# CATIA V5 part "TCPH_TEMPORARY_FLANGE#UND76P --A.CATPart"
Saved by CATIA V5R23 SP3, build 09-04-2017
Part number: TCPH_TEMPORARY_FLANGE#UND758
Revision: --A
Nomenclature: _
Description: TCPH_TEMPORARY_FLANGE
Property "ID": "UND758"
Property "AT": "PD"
Property "REP": "CM"
Property "External Part ID": "_"
Property "Description Modification": "FDR Model"
Property "PREF": "Y"
Property "LONG": "_"
Property "PBS 1": "24"
Property "PBS 2": "CR"
Property "PBS 3": "LC"
Property "DEPT": "_"
Property "DIVN": "_"
Property "GROUP": "_"
Property "UNIT": "_"
Property "PARTY": "_"
Property "RO": "BHARDWA"
Property "RE": "VITUPIG"
Property "PRO": "---"
Property "Change Type": "Minor"
Property "Maturity Level": "CD"
Property "Export Number": "_"
Property "Description Documents": "_"
Property "BOM": "_"
Property "User In Enovia": "VAUQUEJ"
Property "Object Type": "_"
Property "CADENAS_ID": "_"
Property "Life Cycle Status": "Approved"
Bounding box of the stored display mesh (mm): x 16800 to 17545, y -1350 to 1350, z -6273 to -2983
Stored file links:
  C:\Users\pandeym\Desktop\__TCPH\TCPH_TEMPORARY_FLANGE#UND76P --A.CATPart
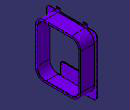
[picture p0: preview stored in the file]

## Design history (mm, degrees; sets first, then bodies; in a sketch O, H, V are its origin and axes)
Set1
  Sketch1 "CR_DOCKING_PORT_CONTACT_INNER_SHELL", origin (17545, 0, 0), H (0, 1, 0), V (0, 0, 1), geometry linked from another document
  Sketch2 "CR_DOCKING_PORT_CONTACT_OUTER_SHELL", origin (17545, 0, 0), H (0, 1, 0), V (0, 0, 1), geometry linked from another document
  Sketch3 "CR_DOCKING_FLANGE_HOLES", origin (17545, 0, 0), H (0, 1, 0), V (0, 0, 1), geometry linked from another document
  Plane1 "CR_DOCKING_PORT_CONNECTING_PLANE": linked copy from another document
  Sketch4 "TEMPORARY_FLANGE_INTERFACE", origin (16800, 0, 0), H (0, 1, 0), V (0, 0, 1), geometry linked from another document
  Sketch5 "TEMPORARY_FLANGE_HOLES", origin (16800, 0, 0), H (0, 1, 0), V (0, 0, 1), geometry linked from another document
  Sketch6 "TEMP_FLANGE_SEALING_GROOVE", origin (16800, 0, 0), H (0, 1, 0), V (0, 0, 1), geometry linked from another document
Body1 (main body)
  Pad1: profile Sketch4, direction (1, 0, 0), length 20
  Sketch7 on Plane1, origin (17545, 0, 0), H (0, 1, 0), V (0, 0, 1)
  Pad2: profile Sketch7, direction (-1, 0, 0), length 20
  Pad3: profile Sketch2, direction (1, 0, 0), up to end face of Pad1, thin wall 20
  Sketch8 on end face of Pad1, origin (16820, 0, -3163), H (0, 1, 0), V (0, 0, 1)
    point P1 (0, 0)
    reference projected point E1 (0, 0) from vertex of Sketch5
    coincidence: E1 P1
  Hole1: placed by Sketch8, at (16820, 0, -3163) direction (-1, 0, 0), diameter 22, through (limit type 3)
  UserPattern1: of Hole1, copies 49, at the points of Sketch5
  Sketch9 on start face of Pad2, origin (17545, -515.117, -3270), H (0, 1, 0), V (0, 0, 1)
    point P1 (0, 0)
    reference projected point E1 (0, 0) from vertex of Sketch3
    coincidence: E1 P1
  Hole2: placed by Sketch9, at (17545, -515.117, -3270) direction (-1, 0, 0), diameter 22, through (limit type 3)
  UserPattern2: of Hole2, copies 36, at the points of Sketch3
  Sketch10 on start face of Pad1, origin (16800, 0, 0), H (0, -1, 0), V (0, 0, 1)
    construction line L1 (-740, -3058) -> (-710, -3058)
    point P1 (-740, -3058)
    line L2 (-740, -3033) -> (-710, -3033)
    line L3 (-710, -3083) -> (-740, -3083)
    arc A1 centre (-710, -3058) radius 25 from (-710, -3033) to (-710, -3083) cw
    arc A2 centre (-740, -3058) radius 25 from (-740, -3083) to (-740, -3033) cw
    reference projected circle E1 centre (-725, -3058) radius 25 from edge [face of Pad1 | start face of Pad1]
    reference projected point E2 (-725, -3058) from axis of face of Pad1
    reference projected point E3 (-725, -3058) from axis of face of Pad1
    length L1 = 30
    distance E3 P1 = 15
    horizontal: L1 H
    tangency: A1 L2, A2 L2, A1 L3, A2 L3, E1 L2
    coincidence: L1 E2
    parallelism: L2 L3
  Pocket1: profile Sketch10, direction (1, 0, 0), through (limit type 3)
  Thickness1: Face (face of Pad1; face of Pocket1 from Sketch10.A1), Thickness -0.5
  Sketch11 on zx-plane, origin (0, 0, 0), H (-1, 0, 0), V (0, 0, 1)
    line L1 (-16800, -3185.875) -> (-16800, -3194.125)
    line L2 (-16800, -3194.125) -> (-16806.5899, -3197.059)
    line L3 (-16808.7, -3195.6887) -> (-16808.7, -3184.3113)
    line L4 (-16806.5899, -3182.941) -> (-16800, -3185.875)
    axis line L5 (-16779.7063, -3190) -> (-16822.2591, -3190)
    reference projected line E1 (-16800, -3343) -> (-16800, -3133) from edge of Sketch4
    reference projected point E2 (-16800, -3190) from edge of Sketch6
    arc A1 centre (-16807.2, -3184.3113) radius 1.5 from (-16808.7, -3184.3113) to (-16806.5899, -3182.941) cw
    arc A2 centre (-16807.2, -3195.6887) radius 1.5 from (-16806.5899, -3197.059) to (-16808.7, -3195.6887) cw
    distance L1 L3 = 8.7
    angle L4 L2 = 48
    length L1 = 8.25
    radius A1 = 1.5
    radius A2 = 1.5
    vertical: L1 V, L3 V
    horizontal: L5 H
    symmetry: L4 L2 L5
    coincidence: L1 E1, L5 E2
    tangency: A1 L3, A1 L4, A2 L2, A2 L3
  Slot1: profile Sketch11, centre curve Sketch6
  Fillet1: radius 0.5, on edge [face of Slot1 | start face of Pad1]; edge [start face of Pad1 | face of Slot1]
  Sketch12 on start face of Pad1, origin (16800, 0, 0), H (0, -1, 0), V (0, 0, 1)
    circle A1 centre (0, -5363) radius 7.5
    point P1 (0, -5363)
    reference projected line E1 (425, -5333) -> (-425, -5333) from edge [face of Pad1 | start face of Pad1]
    distance P1 E1 = 30
    radius A1 = 7.5
    coincidence: P1 V
  Pocket2: profile Sketch12, direction (1, 0, 0), up to face of Slot1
